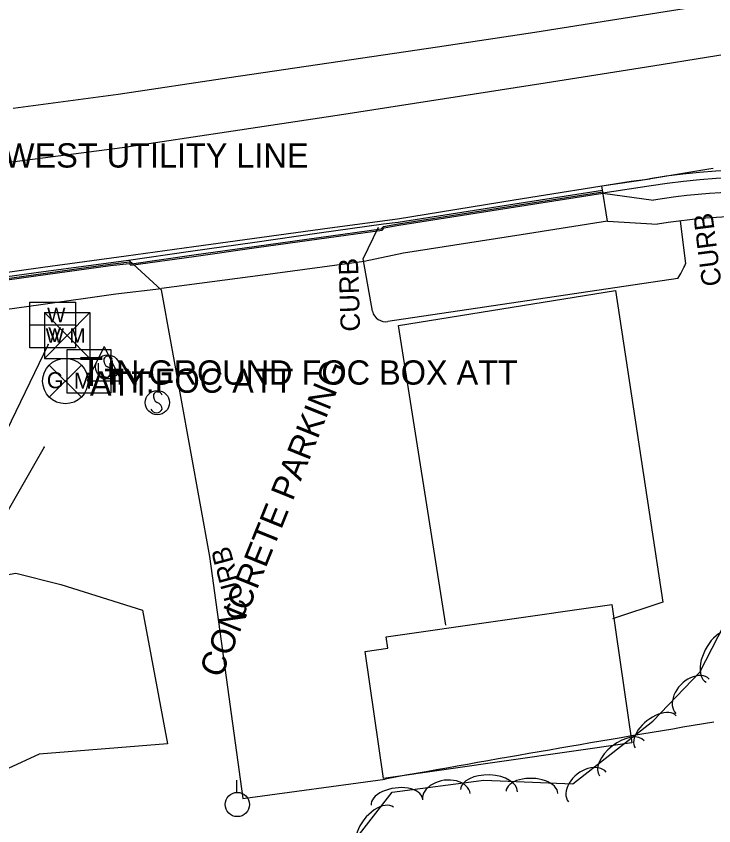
# Model space of a CAD drawing. Extents: x 978516 to 993312, y 1836504 to 1846212.
# Drawn here: x 982364.1 to 982507.9, y 1842469.1 to 1842635.9 of the extents above; entities that cross this region are included whole.
import ezdxf

# ---------------------------------------------------------------- set-up
doc = ezdxf.new("R2010")
doc.units = 0
for name, color, linetype in [('R_Proposed Road', 7, 'Continuous'), ('S_BUILDING', 7, 'Continuous'), ('S_CURB', 7, 'Continuous'), ('S_CURB_ANNOT', 7, 'Continuous'), ('S_EDGE_PAVEMENT', 7, 'Continuous'), ('S_ELECTRIC_UTILITIES_ANNOT', 7, 'Continuous'), ('S_GAS_UTILITIES', 7, 'Continuous'), ('S_MISC_STRUCTURES', 7, 'Continuous'), ('S_MISC_STRUCTURES_ANNOT', 7, 'Continuous'), ('S_PARKING', 7, 'Continuous'), ('S_PARKING_ANNOT', 7, 'Continuous'), ('S_PAVEMENT_CROWN', 7, 'Continuous'), ('S_SIDEWALK', 7, 'Continuous'), ('S_SIGN', 7, 'Continuous'), ('S_TELEPHONE_UTILITIES', 7, 'Continuous'), ('S_TELEPHONE_UTILITIES_ANNOT', 7, 'Continuous'), ('S_TREE', 7, 'Continuous'), ('S_UNDERGROUND_CABLE', 7, 'Continuous'), ('S_UTILITY_POLE', 7, 'Continuous'), ('S_UTILITY_POLE_ANNOT', 7, 'Continuous'), ('S_UTL_PT_SYM', 7, 'Continuous'), ('S_WATER_UTILITIES', 7, 'Continuous')]:
    doc.layers.add(name, color=color, linetype=linetype)

msp = doc.modelspace()

# ---------------------------------------------------------------- linework, layer by layer
at = {"layer": 'R_Proposed Road'}
for p, q in [((982484.81, 1842600.89), (982494.7, 1842602.37)), ((982485.98, 1842593.61), (982484.81, 1842600.89)), ((982494.95, 1842600.89), (982485.05, 1842599.39)), ((982485.05, 1842599.39), (982495.45, 1842597.93)), ((982485.98, 1842593.61), (982496.28, 1842593))]:
    msp.add_line(p, q, dxfattribs=at)
for radius, start in [(130, 3.7353), (128.5, 3.7353), (125.5, 65.7011), (120.5, 65.7011)]:
    msp.add_arc((982516.24, 1842474.17), radius, start, 99.5363, dxfattribs=at)
at = {"layer": 'S_BUILDING'}
msp.add_lwpolyline([(982490.97, 1842486.19), (982439.82, 1842478.84), (982436.06, 1842504.98), (982440.7, 1842505.65), (982440.36, 1842507.97), (982486.88, 1842514.65)], close=True, dxfattribs=at)
at = {"layer": 'S_CURB'}
for points in [[(982304.42, 1842535.98), (982303.95, 1842536.4), (982304.37, 1842537.95), (982307.03, 1842545.57), (982308.22, 1842548.13), (982310.81, 1842552.61), (982313.37, 1842556.57), (982315.95, 1842560.09), (982322.81, 1842567.3), (982329.76, 1842572.5), (982339.82, 1842577.44), (982352.71, 1842580.95), (982369.73, 1842583.25), (982386.76, 1842585.55), (982400.02, 1842587.44), (982413.29, 1842589.33), (982426.56, 1842591.21), (982439.83, 1842593.1), (982442.85, 1842593.45), (982466.9, 1842597.19), (982484.96, 1842599.99)], [(982304.87, 1842538.03), (982307.35, 1842545.41), (982308.61, 1842548.09), (982311.06, 1842552.48), (982313.43, 1842556.24), (982316.2, 1842559.9), (982323.1, 1842567.03), (982329.85, 1842572.11), (982340.17, 1842577.24), (982352.8, 1842580.52), (982368.16, 1842582.67), (982383.51, 1842584.81), (982387.48, 1842585.26), (982387.87, 1842584.87), (982400.75, 1842586.68), (982413.62, 1842588.48), (982426.5, 1842590.28), (982439.37, 1842592.09), (982439.81, 1842592.52), (982442.92, 1842593.1), (982466.98, 1842596.86), (982485.01, 1842599.68)], [(982305.15, 1842537.93), (982307.63, 1842545.3), (982308.88, 1842547.95), (982311.31, 1842552.33), (982313.68, 1842556.07), (982316.43, 1842559.7), (982323.3, 1842566.8), (982330, 1842571.85), (982340.27, 1842576.96), (982352.85, 1842580.23), (982368.2, 1842582.37), (982383.55, 1842584.51), (982387.37, 1842584.94), (982387.77, 1842584.55), (982400.7, 1842586.37), (982413.64, 1842588.18), (982426.58, 1842589.99), (982439.51, 1842591.81), (982439.96, 1842592.25), (982442.97, 1842592.8), (982467.03, 1842596.57), (982485.05, 1842599.39)]]:
    msp.add_lwpolyline(points, dxfattribs=at)
at = {"layer": 'S_EDGE_PAVEMENT'}
msp.add_lwpolyline([(982352.52, 1842581.77), (982369.63, 1842584.15), (982386.75, 1842586.52), (982400.74, 1842588.43), (982414.73, 1842590.34), (982428.73, 1842592.24), (982442.72, 1842594.15), (982466.78, 1842598), (982490.84, 1842601.85), (982493.7, 1842602.2), (982506.89, 1842604.42), (982507.78, 1842604.57)], dxfattribs=at)
at = {"layer": 'S_GAS_UTILITIES'}
for p, q in [((982370.94, 1842557.38), (982377.56, 1842564)), ((982370.94, 1842564), (982377.56, 1842557.38)), ((982369.88, 1842547.06), (982296.84, 1842419.66))]:
    msp.add_line(p, q, dxfattribs=at)
msp.add_circle((982374.25, 1842560.69), 4.68, dxfattribs=at)
at = {"layer": 'S_MISC_STRUCTURES'}
msp.add_lwpolyline([(982452.65, 1842510.42), (982442.89, 1842572.14), (982487.65, 1842579.33), (982497.37, 1842515.11), (982487.03, 1842511.71)], dxfattribs=at)
at = {"layer": 'S_PARKING'}
for points in [[(982500.93, 1842593.69), (982502.07, 1842584.86)], [(982437.53, 1842575.07), (982435.64, 1842585.91), (982438.76, 1842592.39)], [(982387.42, 1842585.55), (982394.02, 1842579.5), (982403.99, 1842524.53), (982410.86, 1842474.72), (982440.19, 1842478.7)], [(982500.47, 1842581.84), (982440.74, 1842572.94)], [(982293.76, 1842507.44), (982303.23, 1842500.15), (982308.05, 1842498.57), (982316.13, 1842500.08), (982342.48, 1842511.76), (982357.09, 1842519.89), (982364.05, 1842521.14), (982373.29, 1842518.79), (982390.17, 1842513.46), (982395.32, 1842485.93), (982368.86, 1842483.8), (982354.21, 1842477.11), (982341.96, 1842472.46), (982329.84, 1842472.23), (982307.08, 1842483.95), (982298.56, 1842486.71), (982292.94, 1842487.52), (982283.26, 1842482.24)]]:
    msp.add_lwpolyline(points, dxfattribs=at)
for centre, major_axis, ratio, start_param, end_param in [((982501.04, 1842583.88), (1.5, 2.99), 0.155645, 4.039042, 5.122538), ((982440.29, 1842575.77), (1.52, -2.44), 0.990036, 4.403266, 5.880152), ((982866.26, 1840403.88), (-3293.44, -535.73), 0.634467, 4.717997, 4.738592)]:
    msp.add_ellipse(centre, major_axis=major_axis, ratio=ratio, start_param=start_param, end_param=end_param, dxfattribs=at)
at = {"layer": 'S_PAVEMENT_CROWN'}
for points in [[(982363.48, 1842616.91), (982385.15, 1842619.83), (982408.03, 1842623.21), (982430.9, 1842626.59), (982450.94, 1842629.58), (982470.99, 1842632.58), (982493.51, 1842636.18), (982516.04, 1842639.79), (982531.79, 1842642.5), (982547.53, 1842645.22), (982568.26, 1842648.38), (982588.99, 1842651.54), (982613.49, 1842655.48), (982637.99, 1842659.42), (982650.48, 1842661.23), (982662.97, 1842663.04), (982675.46, 1842664.85)], [(982342.71, 1842603.24), (982364.35, 1842606.03), (982385.98, 1842608.82), (982408.81, 1842612.24), (982431.64, 1842615.66), (982452.39, 1842618.9), (982473.14, 1842622.13), (982495.31, 1842625.65), (982517.48, 1842629.18), (982533.48, 1842631.7), (982549.48, 1842634.22), (982569.95, 1842637.63), (982590.42, 1842641.04), (982614.83, 1842644.97), (982639.23, 1842648.9), (982651.71, 1842650.73), (982664.2, 1842652.56), (982676.68, 1842654.39)]]:
    msp.add_lwpolyline(points, dxfattribs=at)
at = {"layer": 'S_SIDEWALK'}
for points in [[(982485.98, 1842593.61), (982468.22, 1842590.84), (982443.96, 1842587.05)], [(982443.96, 1842587.05), (982435.8, 1842585.33)], [(982443.96, 1842587.05), (982435.8, 1842585.33)], [(982435.8, 1842585.33), (982414.95, 1842582.54), (982394.09, 1842579.74)], [(982306.16, 1842539.88), (982311.2, 1842538.43), (982312.63, 1842543.13), (982316.18, 1842549.13), (982318.91, 1842552.93), (982321.14, 1842555.84), (982326.7, 1842562.15), (982332.46, 1842566.98), (982342.25, 1842571.33), (982353.84, 1842574.33), (982369.23, 1842576.49), (982384.63, 1842578.66), (982394.09, 1842579.74)]]:
    msp.add_lwpolyline(points, dxfattribs=at)
at = {"layer": 'S_SIGN'}
for centre in [(982382.96, 1842563.61), (982393.21, 1842556.26)]:
    msp.add_circle(centre, 2.49, dxfattribs=at)
for centre, radius, start, end in [((982383.65, 1842564.94), 1.5, 167.1196, 241.9813), ((982383.04, 1842564.88), 0.95, 16.5258, 156.8957), ((982382.55, 1842562.27), 1.4, 358.6529, 73.7063), ((982382.81, 1842562.79), 1.28, 204.641, 335.359), ((982393.89, 1842557.59), 1.5, 167.1196, 241.9813), ((982393.28, 1842557.53), 0.95, 16.5258, 156.8957), ((982392.8, 1842554.92), 1.4, 358.6529, 73.7063), ((982393.05, 1842555.44), 1.28, 204.641, 335.359)]:
    msp.add_arc(centre, radius, start, end, dxfattribs=at)
at = {"layer": 'S_TELEPHONE_UTILITIES'}
msp.add_lwpolyline([(982374.59, 1842558.18), (982374.59, 1842567.18), (982383.59, 1842567.18), (982383.59, 1842558.18)], close=True, dxfattribs=at)
at = {"layer": 'S_TREE'}
msp.add_lwpolyline([(982418.09, 1842384.04), (982415.54, 1842415.3), (982409.89, 1842435.09), (982414.58, 1842455.38), (982434.89, 1842467.34), (982441.62, 1842475.99), (982460.5, 1842478.49), (982478.83, 1842477.72), (982495.31, 1842490.64), (982505.01, 1842500.72), (982522.69, 1842535.08), (982538.68, 1842548.92), (982553.17, 1842539.7), (982563.88, 1842520.52), (982573.46, 1842505.65), (982583.33, 1842488.7), (982594.21, 1842474.58), (982608.32, 1842467.31), (982624.78, 1842470.47), (982643.08, 1842474.77), (982654.04, 1842474.13), (982665.31, 1842463.88), (982684.43, 1842452.69)], dxfattribs=at)
for centre, major_axis, ratio, start_param, end_param in [((982509, 1842503.86), (-2.69, -5.22), 0.550043, 3.142249, 6.283842), ((982503.52, 1842495.75), (-3.43, -3.55), 0.687879, 3.145706, 6.287299), ((982495.91, 1842488.43), (-4.2, -3.29), 0.541056, 3.142924, 6.284517), ((982488.95, 1842482.96), (-4.61, -3.61), 0.550443, 3.142968, 6.28456), ((982481.83, 1842477.05), (-3.9, -3.05), 0.685762, 3.143846, 6.285439), ((982461.56, 1842476.32), (-5.85, 0.24), 0.55089, 3.140208, 6.2818), ((982452.79, 1842475.07), (-4.9, -0.66), 0.68651, 3.138842, 6.280435), ((982470.4, 1842475.95), (-5.33, 0.22), 0.541496, 3.140251, 6.281844), ((982442.56, 1842473.98), (-5.29, -0.7), 0.541647, 3.139969, 6.281562), ((982438.33, 1842468.32), (-3.54, -4.57), 0.558153, 3.136924, 6.278517)]:
    msp.add_ellipse(centre, major_axis=major_axis, ratio=ratio, start_param=start_param, end_param=end_param, dxfattribs=at)
at = {"layer": 'S_UNDERGROUND_CABLE'}
for p, q in [((982382.26, 1842567.81), (982378.73, 1842560.72)), ((982382.26, 1842567.81), (982385.74, 1842560.72)), ((982381.05, 1842561.96), (982381.05, 1842564.4)), ((982383.42, 1842564.4), (982383.42, 1842561.96)), ((982381.67, 1842561.3), (982381.05, 1842561.96)), ((982382.88, 1842561.3), (982381.67, 1842561.3)), ((982383.42, 1842561.96), (982382.88, 1842561.3)), ((982378.73, 1842560.72), (982385.74, 1842560.72))]:
    msp.add_line(p, q, dxfattribs=at)
at = {"layer": 'S_UTILITY_POLE'}
msp.add_line((982409.56, 1842475.97), (982409.56, 1842478.45), dxfattribs=at)
msp.add_circle((982409.7, 1842473.45), 2.5, dxfattribs=at)
at = {"layer": 'S_UTL_PT_SYM'}
for points in [[(982370.72, 1842568.26), (982370.72, 1842568.31), (982370.72, 1842568.26), (982370.67, 1842568.26), (982370.72, 1842568.26), (982370.72, 1842568.21), (982370.72, 1842568.26), (982370.77, 1842568.26)], [(982369.88, 1842547.06), (982369.88, 1842547.11), (982369.88, 1842547.06), (982369.83, 1842547.06), (982369.88, 1842547.06), (982369.88, 1842547.01), (982369.88, 1842547.06), (982369.93, 1842547.06)]]:
    msp.add_lwpolyline(points, dxfattribs=at)
at = {"layer": 'S_WATER_UTILITIES'}
for p, q in [((982366.94, 1842576.98), (982376.35, 1842576.98)), ((982366.94, 1842567.56), (982366.94, 1842576.98)), ((982376.35, 1842576.98), (982376.35, 1842567.56)), ((982369.98, 1842574.82), (982379.32, 1842574.82)), ((982369.98, 1842574.82), (982369.98, 1842565.33)), ((982369.98, 1842574.82), (982379.32, 1842565.33)), ((982379.32, 1842574.82), (982369.98, 1842565.33)), ((982379.32, 1842574.82), (982379.32, 1842565.33)), ((982366.94, 1842572.29), (982376.35, 1842572.29)), ((982370.72, 1842568.26), (982336.29, 1842497.04)), ((982376.35, 1842567.56), (982366.94, 1842567.56)), ((982369.98, 1842565.33), (982379.32, 1842565.33))]:
    msp.add_line(p, q, dxfattribs=at)

# ---------------------------------------------------------------- texts
at = {"layer": 'S_CURB_ANNOT'}
for rotation, p in [(97.246, (982509.51, 1842580.48)), (91.7694, (982435.01, 1842570.95)), (105.2064, (982412.01, 1842512.29))]:
    msp.add_text('CURB', height=4, rotation=rotation, dxfattribs=at).set_placement(p)
at = {"layer": 'S_ELECTRIC_UTILITIES_ANNOT'}
msp.add_text('LOWEST UTILITY LINE', height=5, dxfattribs=at).set_placement((982352.67, 1842604.68))
at = {"layer": 'S_GAS_UTILITIES'}
for s, p in [('G', (982370.43, 1842559.22)), ('M', (982376, 1842559.12))]:
    msp.add_text(s, height=3.3, dxfattribs=at).set_placement(p)
at = {"layer": 'S_MISC_STRUCTURES_ANNOT'}
msp.add_text('IN GROUND FOC BOX ATT', height=5, dxfattribs=at).set_placement((982382.82, 1842559.96))
at = {"layer": 'S_PARKING_ANNOT'}
msp.add_text('CONCRETE PARKING', height=5.0005, rotation=68.0408, dxfattribs=at).set_placement((982406.36, 1842499.29))
at = {"layer": 'S_TELEPHONE_UTILITIES'}
msp.add_text('T', height=6, dxfattribs=at).set_placement((982377.15, 1842559.68))
at = {"layer": 'S_TELEPHONE_UTILITIES_ANNOT'}
msp.add_text('ATT', height=5, dxfattribs=at).set_placement((982379.31, 1842557.7))
at = {"layer": 'S_UTILITY_POLE_ANNOT'}
msp.add_text('TY:FOC ATT', height=5, dxfattribs=at).set_placement((982382.26, 1842558.28))
at = {"layer": 'S_WATER_UTILITIES'}
for s, p in [('W', (982370.49, 1842572.82)), ('W M', (982370.19, 1842568.59)), ('V', (982370.72, 1842568.76))]:
    msp.add_text(s, height=3, dxfattribs=at).set_placement(p)

doc.saveas('drawing.dxf')
